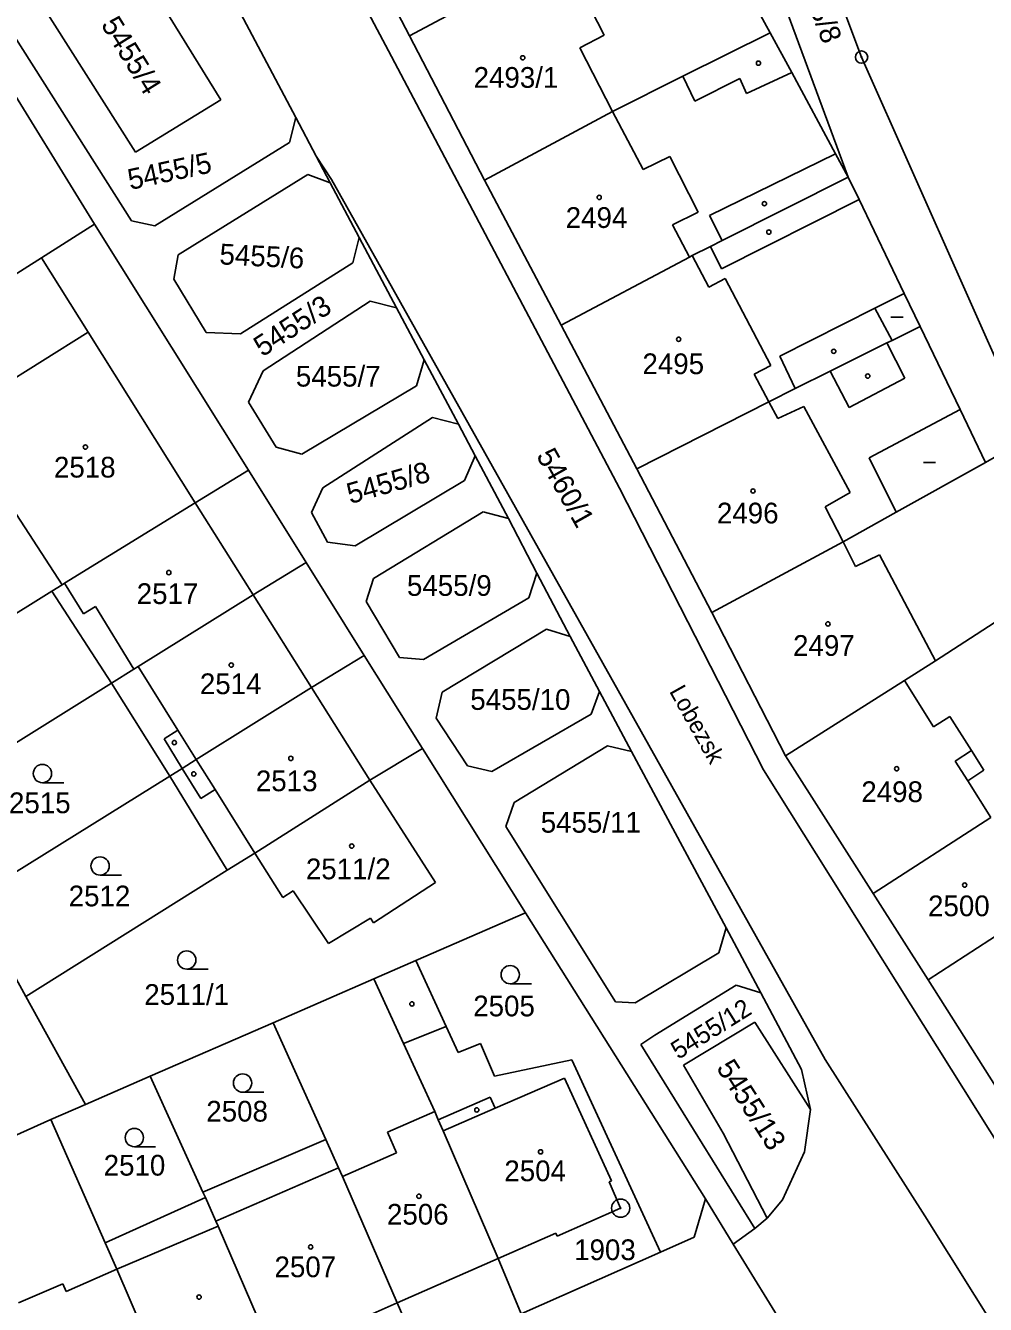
# Model space of a CAD drawing. Extents: x -822293 to -820259, y -1071573 to -1068794.
# Drawn here: x -820751.7 to -820673, y -1071232.4 to -1071127.6 of the extents above; entities that cross this region are included whole.
import ezdxf

# ---------------------------------------------------------------- set-up
doc = ezdxf.new("R2010")
doc.units = 0
for name, color, linetype in [('Vrstva 1', 7, 'Continuous'), ('Vrstva 15', 7, 'Continuous'), ('Vrstva 16', 7, 'Continuous'), ('Vrstva 17', 7, 'Continuous'), ('Vrstva 18', 7, 'Continuous'), ('Vrstva 19', 7, 'Continuous'), ('Vrstva 2', 7, 'Continuous'), ('Vrstva 24', 7, 'Continuous'), ('Vrstva 25', 7, 'Continuous'), ('Vrstva 3', 7, 'Continuous'), ('Vrstva 4', 7, 'Continuous')]:
    doc.layers.add(name, color=color, linetype=linetype)

msp = doc.modelspace()

# ---------------------------------------------------------------- linework, layer by layer
at = {"layer": 'Vrstva 1'}
for p, q in [((-820734.74, -1071105.53), (-820721.97, -1071129.66)), ((-820686.65, -1071120.86), (-820683.15, -1071130.16)), ((-820753.41, -1071121.15), (-820742.72, -1071137.97)), ((-820691.22, -1071121.15), (-820684.26, -1071140)), ((-820743.05, -1071143.59), (-820756.22, -1071122.85)), ((-820735.43, -1071124.06), (-820729.58, -1071135.12)), ((-820735.71, -1071133.66), (-820741.22, -1071124.78)), ((-820690.65, -1071128.16), (-820692.2, -1071125.31)), ((-820746.09, -1071143.86), (-820755.45, -1071128.7)), ((-820703.01, -1071165.5), (-820721.97, -1071129.66)), ((-820683.15, -1071130.16), (-820669.33, -1071161.28)), ((-820685.28, -1071138.1), (-820688.88, -1071131.43)), ((-820703.6, -1071134.61), (-820697.81, -1071131.73)), ((-820742.72, -1071137.97), (-820735.71, -1071133.66)), ((-820729.58, -1071135.12), (-820730.1, -1071137.16)), ((-820729.58, -1071135.12), (-820727.9, -1071138.28)), ((-820730.1, -1071137.16), (-820741.14, -1071144)), ((-820727.9, -1071138.28), (-820726.63, -1071140.19)), ((-820726.75, -1071140.46), (-820727.9, -1071138.28)), ((-820739.23, -1071146.37), (-820728.58, -1071139.78)), ((-820728.58, -1071139.78), (-820726.75, -1071140.46)), ((-820724.37, -1071144.96), (-820726.75, -1071140.46)), ((-820726.63, -1071140.19), (-820686.13, -1071212.37)), ((-820679.65, -1071149.54), (-820683.36, -1071141.85)), ((-820750.44, -1071146.62), (-820746.09, -1071143.86)), ((-820733.45, -1071164.03), (-820746.09, -1071143.86)), ((-820741.14, -1071144), (-820743.05, -1071143.59)), ((-820724.37, -1071144.96), (-820724.9, -1071147.03)), ((-820721.3, -1071150.72), (-820724.37, -1071144.96)), ((-820697.05, -1071146.44), (-820695.55, -1071145.68)), ((-820759.61, -1071152.44), (-820750.44, -1071146.62)), ((-820746.61, -1071152.71), (-820750.44, -1071146.62)), ((-820739.58, -1071148.36), (-820739.23, -1071146.37)), ((-820724.9, -1071147.03), (-820734.12, -1071152.85)), ((-820736.92, -1071152.74), (-820739.58, -1071148.36)), ((-820732.26, -1071155.89), (-820723.48, -1071150.17)), ((-820723.48, -1071150.17), (-820721.3, -1071150.72)), ((-820719.03, -1071154.99), (-820721.3, -1071150.72)), ((-820678.34, -1071152.24), (-820675.07, -1071159.07)), ((-820734.12, -1071152.85), (-820736.92, -1071152.74)), ((-820719.03, -1071154.99), (-820719.68, -1071157.13)), ((-820716.23, -1071160.25), (-820719.03, -1071154.99)), ((-820733.46, -1071158.47), (-820732.26, -1071155.89)), ((-820719.68, -1071157.13), (-820729.09, -1071162.72)), ((-820690.77, -1071158.42), (-820688.61, -1071157.34)), ((-820731.17, -1071162.15), (-820733.46, -1071158.47)), ((-820727.36, -1071165.47), (-820718.35, -1071159.72)), ((-820718.35, -1071159.72), (-820716.23, -1071160.25)), ((-820714.86, -1071162.86), (-820716.23, -1071160.25)), ((-820672.99, -1071163.41), (-820669.33, -1071161.28)), ((-820729.09, -1071162.72), (-820731.17, -1071162.15)), ((-820714.86, -1071162.86), (-820715.72, -1071164.88)), ((-820712.13, -1071168.01), (-820714.86, -1071162.86)), ((-820733.45, -1071164.03), (-820737.82, -1071166.7)), ((-820728.72, -1071171.6), (-820733.45, -1071164.03)), ((-820715.72, -1071164.88), (-820724.71, -1071170.23)), ((-820728.29, -1071167.5), (-820727.36, -1071165.47)), ((-820691.2, -1071188.61), (-820703.01, -1071165.5)), ((-820726.97, -1071169.93), (-820728.29, -1071167.5)), ((-820723.2, -1071172.93), (-820714.21, -1071167.44)), ((-820714.21, -1071167.44), (-820712.13, -1071168.01)), ((-820709.79, -1071172.49), (-820712.13, -1071168.01)), ((-820684.65, -1071169.9), (-820680.32, -1071167.47)), ((-820724.71, -1071170.23), (-820726.97, -1071169.93)), ((-820728.72, -1071171.6), (-820733.07, -1071174.25)), ((-820723.95, -1071179.23), (-820728.72, -1071171.6)), ((-820748.75, -1071173.43), (-820749.58, -1071173.96)), ((-820723.79, -1071174.81), (-820723.2, -1071172.93)), ((-820709.79, -1071172.49), (-820710.46, -1071174.49)), ((-820707.06, -1071177.66), (-820709.79, -1071172.49)), ((-820749.58, -1071173.96), (-820764.83, -1071183.43)), ((-820749.58, -1071173.96), (-820744.7, -1071181.5)), ((-820710.46, -1071174.49), (-820719.09, -1071179.55)), ((-820721.07, -1071179.4), (-820723.79, -1071174.81)), ((-820677.09, -1071179.67), (-820672.26, -1071176.55)), ((-820717.55, -1071182.25), (-820708.99, -1071177.07)), ((-820708.99, -1071177.07), (-820707.06, -1071177.66)), ((-820704.64, -1071182.18), (-820707.06, -1071177.66)), ((-820723.95, -1071179.23), (-820728.29, -1071181.85)), ((-820719.18, -1071186.85), (-820723.95, -1071179.23)), ((-820719.09, -1071179.55), (-820721.07, -1071179.4)), ((-820742.85, -1071180.34), (-820744.7, -1071181.5)), ((-820744.7, -1071181.5), (-820760.46, -1071191.35)), ((-820744.7, -1071181.5), (-820739.92, -1071189.13)), ((-820718.06, -1071184.38), (-820717.55, -1071182.25)), ((-820704.64, -1071182.18), (-820705.34, -1071184.04)), ((-820702.02, -1071187.09), (-820704.64, -1071182.18)), ((-820715.48, -1071188.28), (-820718.06, -1071184.38)), ((-820705.34, -1071184.04), (-820713.49, -1071188.75)), ((-820719.18, -1071186.85), (-820723.51, -1071189.45)), ((-820710.73, -1071200.33), (-820719.18, -1071186.85)), ((-820704, -1071186.65), (-820711.66, -1071191.28)), ((-820702.02, -1071187.09), (-820704, -1071186.65)), ((-820694.27, -1071201.56), (-820702.02, -1071187.09)), ((-820739.92, -1071189.13), (-820756.13, -1071199.21)), ((-820738.89, -1071188.49), (-820739.92, -1071189.13)), ((-820739.92, -1071189.13), (-820735.19, -1071196.84)), ((-820713.49, -1071188.75), (-820715.48, -1071188.28)), ((-820671.47, -1071220.04), (-820691.2, -1071188.61)), ((-820711.66, -1071191.28), (-820712.35, -1071193.24)), ((-820712.35, -1071193.24), (-820703.35, -1071207.63)), ((-820732.94, -1071195.44), (-820735.19, -1071196.84)), ((-820735.19, -1071196.84), (-820751.73, -1071207.19)), ((-820710.73, -1071200.33), (-820719.73, -1071204.25)), ((-820695.95, -1071223.78), (-820710.73, -1071200.33)), ((-820694.85, -1071203.6), (-820694.27, -1071201.56)), ((-820691.41, -1071206.9), (-820694.27, -1071201.56)), ((-820701.73, -1071207.7), (-820694.85, -1071203.6)), ((-820751.73, -1071207.19), (-820752.85, -1071205.14)), ((-820723.18, -1071205.75), (-820731.44, -1071209.34)), ((-820693.45, -1071206.27), (-820700.1, -1071210.35)), ((-820691.41, -1071206.9), (-820693.45, -1071206.27)), ((-820688.08, -1071213.18), (-820691.41, -1071206.9)), ((-820746.84, -1071216.04), (-820751.73, -1071207.19)), ((-820703.35, -1071207.63), (-820701.73, -1071207.7)), ((-820731.44, -1071209.34), (-820741.52, -1071213.72)), ((-820727.11, -1071218.91), (-820731.44, -1071209.34)), ((-820716.25, -1071211.79), (-820717.24, -1071209.64)), ((-820691.91, -1071209.29), (-820697.76, -1071212.83)), ((-820687.34, -1071216.45), (-820691.91, -1071209.29)), ((-820720.73, -1071211.06), (-820718.17, -1071216.61)), ((-820714.42, -1071211.06), (-820716.25, -1071211.79)), ((-820713.26, -1071213.73), (-820714.42, -1071211.06)), ((-820700.1, -1071210.35), (-820701.25, -1071211.14)), ((-820701.25, -1071211.14), (-820691.91, -1071226.22)), ((-820706.91, -1071212.38), (-820713.26, -1071213.73)), ((-820699.66, -1071228.17), (-820706.91, -1071212.38)), ((-820697.76, -1071212.83), (-820694.5, -1071218.41)), ((-820687.34, -1071216.45), (-820688.08, -1071213.18)), ((-820686.13, -1071212.37), (-820677.95, -1071225.19)), ((-820741.52, -1071213.72), (-820746.84, -1071216.04)), ((-820741.52, -1071213.72), (-820737.19, -1071223.25)), ((-820746.84, -1071216.04), (-820749.66, -1071217.29)), ((-820687.82, -1071219.92), (-820687.34, -1071216.45)), ((-820749.66, -1071217.29), (-820757.43, -1071220.74)), ((-820745.21, -1071227.39), (-820749.66, -1071217.29)), ((-820694.5, -1071218.41), (-820690.91, -1071225.38)), ((-820737.19, -1071223.25), (-820727.11, -1071218.91)), ((-820726.06, -1071221.23), (-820727.11, -1071218.91)), ((-820689.63, -1071223.86), (-820687.82, -1071219.92)), ((-820745.21, -1071227.39), (-820736.99, -1071223.68)), ((-820737.19, -1071223.25), (-820736.99, -1071223.68)), ((-820736.99, -1071223.68), (-820736.12, -1071225.62)), ((-820696.89, -1071226.94), (-820695.95, -1071223.78)), ((-820693.68, -1071227.51), (-820695.95, -1071223.78)), ((-820690.91, -1071225.38), (-820689.63, -1071223.86)), ((-820691.91, -1071226.22), (-820690.91, -1071225.38)), ((-820622.76, -1071313.08), (-820677.95, -1071225.19)), ((-820699.66, -1071228.17), (-820696.89, -1071226.94)), ((-820693.68, -1071227.51), (-820691.91, -1071226.22)), ((-820744.25, -1071229.56), (-820745.21, -1071227.39)), ((-820688.09, -1071236.58), (-820693.68, -1071227.51)), ((-820712.97, -1071228.69), (-820711.07, -1071233.22)), ((-820711.07, -1071233.22), (-820699.66, -1071228.17)), ((-820719.29, -1071236.82), (-820721.25, -1071232.32))]:
    msp.add_line(p, q, dxfattribs=at)
at = {"layer": 'Vrstva 2'}
for p, q in [((-820726.4, -1071116.5), (-820720.24, -1071128.42)), ((-820720.24, -1071128.42), (-820709.67, -1071122.78)), ((-820714.09, -1071140.25), (-820720.24, -1071128.42)), ((-820697.81, -1071131.73), (-820690.65, -1071128.16)), ((-820688.88, -1071131.43), (-820690.65, -1071128.16)), ((-820714.09, -1071140.25), (-820703.6, -1071134.61)), ((-820684.26, -1071140), (-820685.28, -1071138.1)), ((-820707.79, -1071152.15), (-820714.09, -1071140.25)), ((-820694.58, -1071145.2), (-820684.26, -1071140)), ((-820683.36, -1071141.85), (-820684.26, -1071140)), ((-820695.55, -1071145.68), (-820694.58, -1071145.2)), ((-820707.79, -1071152.15), (-820697.27, -1071146.56)), ((-820697.27, -1071146.56), (-820697.05, -1071146.44)), ((-820678.34, -1071152.24), (-820679.65, -1071149.54)), ((-820701.58, -1071163.92), (-820707.79, -1071152.15)), ((-820680.65, -1071153.39), (-820678.34, -1071152.24)), ((-820757.69, -1071159.67), (-820746.61, -1071152.71)), ((-820685.72, -1071155.91), (-820681.07, -1071153.6)), ((-820681.07, -1071153.6), (-820680.65, -1071153.39)), ((-820688.61, -1071157.34), (-820685.72, -1071155.91)), ((-820701.58, -1071163.92), (-820690.77, -1071158.42)), ((-820675.07, -1071159.07), (-820672.99, -1071163.41)), ((-820695.43, -1071175.71), (-820701.58, -1071163.92)), ((-820680.32, -1071167.47), (-820672.99, -1071163.41)), ((-820737.82, -1071166.7), (-820748.54, -1071173.3)), ((-820748.75, -1071173.43), (-820752.48, -1071167.68)), ((-820695.43, -1071175.71), (-820684.65, -1071169.9)), ((-820748.54, -1071173.3), (-820748.75, -1071173.43)), ((-820733.07, -1071174.25), (-820742.51, -1071180.13)), ((-820689.38, -1071187.46), (-820695.43, -1071175.71)), ((-820679.64, -1071181.29), (-820677.09, -1071179.67)), ((-820742.51, -1071180.13), (-820742.85, -1071180.34)), ((-820728.29, -1071181.85), (-820737.74, -1071187.76)), ((-820689.38, -1071187.46), (-820679.64, -1071181.29)), ((-820737.74, -1071187.76), (-820738.89, -1071188.49)), ((-820682.2, -1071198.75), (-820689.38, -1071187.46)), ((-820723.51, -1071189.45), (-820732.94, -1071195.44)), ((-820723.51, -1071189.45), (-820718.1, -1071197.85)), ((-820682.2, -1071198.75), (-820672.54, -1071192.52)), ((-820730.64, -1071199.07), (-820732.94, -1071195.44)), ((-820729.79, -1071198.53), (-820730.64, -1071199.07)), ((-820726.88, -1071202.84), (-820729.79, -1071198.53)), ((-820718.1, -1071197.85), (-820723.2, -1071201.15)), ((-820677.69, -1071205.82), (-820682.2, -1071198.75)), ((-820677.69, -1071205.82), (-820668.05, -1071199.57)), ((-820723.45, -1071200.77), (-820726.88, -1071202.84)), ((-820723.2, -1071201.15), (-820723.45, -1071200.77)), ((-820719.73, -1071204.25), (-820723.18, -1071205.75)), ((-820717.24, -1071209.64), (-820719.73, -1071204.25)), ((-820723.18, -1071205.75), (-820720.73, -1071211.06)), ((-820669.63, -1071218.58), (-820677.69, -1071205.82)), ((-820718.17, -1071216.61), (-820717.88, -1071217.3)), ((-820717.88, -1071217.3), (-820717.48, -1071218.21)), ((-820717.48, -1071218.21), (-820712.97, -1071228.69)), ((-820725.74, -1071221.95), (-820726.06, -1071221.23)), ((-820721.25, -1071232.32), (-820725.74, -1071221.95)), ((-820736.12, -1071225.62), (-820735.94, -1071226.03)), ((-820735.94, -1071226.03), (-820731.32, -1071236.74)), ((-820739.57, -1071240.36), (-820744.25, -1071229.56))]:
    msp.add_line(p, q, dxfattribs=at)
at = {"layer": 'Vrstva 24'}
for centre, radius in [((-820683.15, -1071130.16), 0.5), ((-820683.15, -1071130.16), 0.0327), ((-820702.92, -1071224.55), 0.75), ((-820702.92, -1071224.55), 0.0327)]:
    msp.add_circle(centre, radius, dxfattribs=at)
at = {"layer": 'Vrstva 25'}
for p, q in [((-820680.75, -1071151.49), (-820679.75, -1071151.49)), ((-820678.08, -1071163.4), (-820677.08, -1071163.4)), ((-820748.61, -1071189.66), (-820750.36, -1071189.66)), ((-820743.88, -1071197.24), (-820745.63, -1071197.24)), ((-820736.77, -1071204.95), (-820738.52, -1071204.95)), ((-820710.23, -1071206.15), (-820711.98, -1071206.15)), ((-820732.19, -1071215.04), (-820733.94, -1071215.04)), ((-820741.07, -1071219.51), (-820742.82, -1071219.51))]:
    msp.add_line(p, q, dxfattribs=at)
for centre, radius in [((-820710.95, -1071130.22), 0.175), ((-820691.61, -1071130.66), 0.175), ((-820704.68, -1071141.67), 0.175), ((-820691.12, -1071142.18), 0.175), ((-820690.76, -1071144.51), 0.175), ((-820698.16, -1071153.3), 0.175), ((-820685.43, -1071154.29), 0.175), ((-820682.64, -1071156.32), 0.175), ((-820746.83, -1071162.14), 0.175), ((-820692.06, -1071165.74), 0.175), ((-820739.99, -1071172.43), 0.175), ((-820685.91, -1071176.64), 0.175), ((-820734.87, -1071180.02), 0.175), ((-820739.54, -1071186.37), 0.175), ((-820750.36, -1071188.91), 0.75), ((-820729.98, -1071187.67), 0.175), ((-820737.94, -1071188.94), 0.175), ((-820680.27, -1071188.52), 0.175), ((-820724.98, -1071194.86), 0.175), ((-820745.63, -1071196.49), 0.75), ((-820674.69, -1071198.06), 0.175), ((-820738.52, -1071204.2), 0.75), ((-820711.98, -1071205.4), 0.75), ((-820720.05, -1071207.8), 0.175), ((-820733.94, -1071214.29), 0.75), ((-820714.72, -1071216.49), 0.175), ((-820742.82, -1071218.76), 0.75), ((-820709.49, -1071219.93), 0.175), ((-820719.47, -1071223.57), 0.175), ((-820728.35, -1071227.73), 0.175), ((-820737.51, -1071231.84), 0.175)]:
    msp.add_circle(centre, radius, dxfattribs=at)
at = {"layer": 'Vrstva 3'}
for p, q in [((-820704.26, -1071128.35), (-820706.15, -1071124.68)), ((-820706.28, -1071129.39), (-820704.26, -1071128.35)), ((-820703.6, -1071134.61), (-820706.28, -1071129.39)), ((-820688.88, -1071131.43), (-820692.6, -1071133.15)), ((-820696.84, -1071133.78), (-820697.81, -1071131.73)), ((-820693.14, -1071131.91), (-820696.84, -1071133.78)), ((-820692.6, -1071133.15), (-820693.14, -1071131.91)), ((-820701.07, -1071139.39), (-820703.6, -1071134.61)), ((-820698.88, -1071138.32), (-820701.07, -1071139.39)), ((-820696.55, -1071142.87), (-820698.88, -1071138.32)), ((-820695.63, -1071143.15), (-820685.28, -1071138.1)), ((-820694.63, -1071147.52), (-820683.36, -1071141.85)), ((-820698.66, -1071143.92), (-820696.55, -1071142.87)), ((-820697.27, -1071146.56), (-820698.66, -1071143.92)), ((-820694.58, -1071145.2), (-820695.63, -1071143.15)), ((-820695.55, -1071145.68), (-820694.63, -1071147.52)), ((-820695.69, -1071149.02), (-820697.05, -1071146.44)), ((-820694.33, -1071148.31), (-820695.69, -1071149.02)), ((-820690.59, -1071155.45), (-820694.33, -1071148.31)), ((-820682.06, -1071150.75), (-820679.65, -1071149.54)), ((-820689.87, -1071154.68), (-820682.06, -1071150.75)), ((-820682.06, -1071150.75), (-820680.65, -1071153.39)), ((-820737.82, -1071166.7), (-820746.61, -1071152.71)), ((-820681.07, -1071153.6), (-820679.6, -1071156.49)), ((-820691.95, -1071156.16), (-820690.59, -1071155.45)), ((-820688.61, -1071157.34), (-820689.87, -1071154.68)), ((-820690.77, -1071158.42), (-820691.95, -1071156.16)), ((-820684.17, -1071158.9), (-820685.72, -1071155.91)), ((-820679.6, -1071156.49), (-820684.17, -1071158.9)), ((-820690.02, -1071159.79), (-820690.77, -1071158.42)), ((-820687.88, -1071158.82), (-820690.02, -1071159.79)), ((-820684.09, -1071165.86), (-820687.88, -1071158.82)), ((-820682.54, -1071163.02), (-820675.07, -1071159.07)), ((-820680.32, -1071167.47), (-820682.54, -1071163.02)), ((-820686.14, -1071167.03), (-820684.09, -1071165.86)), ((-820733.07, -1071174.25), (-820737.82, -1071166.7)), ((-820684.65, -1071169.9), (-820686.14, -1071167.03)), ((-820683.66, -1071171.93), (-820684.65, -1071169.9)), ((-820681.68, -1071170.97), (-820683.66, -1071171.93)), ((-820677.09, -1071179.67), (-820681.68, -1071170.97)), ((-820747, -1071175.82), (-820748.54, -1071173.3)), ((-820728.29, -1071181.85), (-820733.07, -1071174.25)), ((-820746, -1071175.2), (-820747, -1071175.82)), ((-820742.85, -1071180.34), (-820746, -1071175.2)), ((-820739.25, -1071185.34), (-820742.51, -1071180.13)), ((-820723.51, -1071189.45), (-820728.29, -1071181.85)), ((-820677.24, -1071185.08), (-820679.64, -1071181.29)), ((-820675.91, -1071184.23), (-820677.24, -1071185.08)), ((-820674.13, -1071187.01), (-820675.91, -1071184.23)), ((-820740.38, -1071186.07), (-820739.25, -1071185.34)), ((-820738.89, -1071188.49), (-820740.38, -1071186.07)), ((-820737.74, -1071187.76), (-820739.25, -1071185.34)), ((-820674.13, -1071187.01), (-820675.47, -1071187.9)), ((-820736.2, -1071190.23), (-820737.74, -1071187.76)), ((-820675.47, -1071187.9), (-820674.44, -1071189.52)), ((-820737.37, -1071190.95), (-820738.89, -1071188.49)), ((-820736.2, -1071190.23), (-820737.37, -1071190.95)), ((-820732.94, -1071195.44), (-820736.2, -1071190.23)), ((-820672.54, -1071192.52), (-820674.44, -1071189.52)), ((-820717.24, -1071209.64), (-820720.73, -1071211.06)), ((-820707.52, -1071213.89), (-820713.22, -1071216.36)), ((-820703.68, -1071222.3), (-820707.52, -1071213.89)), ((-820713.62, -1071215.45), (-820717.88, -1071217.3)), ((-820713.22, -1071216.36), (-820713.62, -1071215.45)), ((-820713.22, -1071216.36), (-820717.48, -1071218.21)), ((-820722.04, -1071218.33), (-820718.17, -1071216.61)), ((-820721.31, -1071220), (-820722.04, -1071218.33)), ((-820725.74, -1071221.95), (-820721.31, -1071220)), ((-820736.12, -1071225.62), (-820726.06, -1071221.23)), ((-820703.86, -1071222.38), (-820703.68, -1071222.3)), ((-820702.92, -1071224.55), (-820703.86, -1071222.38)), ((-820702.92, -1071224.55), (-820708.14, -1071226.84)), ((-820744.25, -1071229.56), (-820735.94, -1071226.03)), ((-820708.24, -1071226.61), (-820712.97, -1071228.69)), ((-820708.14, -1071226.84), (-820708.24, -1071226.61)), ((-820712.97, -1071228.69), (-820721.25, -1071232.32)), ((-820748.42, -1071231.37), (-820744.25, -1071229.56)), ((-820752.32, -1071232.32), (-820748.7, -1071230.75)), ((-820748.7, -1071230.75), (-820748.42, -1071231.37)), ((-820721.25, -1071232.32), (-820731.32, -1071236.74))]:
    msp.add_line(p, q, dxfattribs=at)
at = {"layer": 'Vrstva 4'}
for p, q in [((-820673.11, -1071188.62), (-820674.13, -1071187.01)), ((-820674.44, -1071189.52), (-820673.11, -1071188.62))]:
    msp.add_line(p, q, dxfattribs=at)

# ---------------------------------------------------------------- texts
at = {"layer": 'Vrstva 15'}
msp.add_text('Lobezsk\xa0', height=1.4, rotation=299.2968, dxfattribs=at).set_placement((-820698.964, -1071182.162))
at = {"layer": 'Vrstva 16'}
msp.add_text('2483/8', height=1.7, rotation=290.26548, dxfattribs=at).set_placement((-820688.72, -1071122.666))
at = {"layer": 'Vrstva 17'}
msp.add_text('1903', height=1.7, dxfattribs=at).set_placement((-820706.735, -1071228.81))
at = {"layer": 'Vrstva 18'}
for s, height, rotation, p in [('5455/4', 1.7, 301.8195, (-820745.606, -1071127.498)), ('5455/5', 1.7, 12.1617, (-820743.156, -1071141.062)), ('5455/6', 1.7, 357.05727, (-820735.867, -1071147.152)), ('5455/3', 1.7, 33.08328, (-820732.31, -1071154.79)), ('5460/1', 1.7, 299.2968, (-820709.881, -1071162.841)), ('5455/8', 1.7, 15.83721, (-820725.108, -1071166.821)), ('5455/12', 1.5, 31.97835, (-820698.191, -1071212.398)), ('5455/13', 1.7, 302.54877, (-820695.111, -1071213.046))]:
    msp.add_text(s, height=height, rotation=rotation, dxfattribs=at).set_placement(p)
for s, p in [('5455/7', (-820729.566, -1071157.18)), ('5455/9', (-820720.452, -1071174.34)), ('5455/10', (-820715.256, -1071183.69)), ('2515', (-820753.104, -1071192.16)), ('5455/11', (-820709.476, -1071193.76)), ('2512', (-820748.207, -1071199.8)), ('2511/1', (-820742.003, -1071207.88)), ('2505', (-820715.014, -1071208.82)), ('2508', (-820736.916, -1071217.45)), ('2510', (-820745.336, -1071221.88))]:
    msp.add_text(s, height=1.7, dxfattribs=at).set_placement(p)
at = {"layer": 'Vrstva 19'}
for s, p in [('2493/1', (-820714.982, -1071132.68)), ('2494', (-820707.428, -1071144.17)), ('2495', (-820701.129, -1071156.16)), ('2518', (-820749.416, -1071164.64)), ('2496', (-820695.018, -1071168.4)), ('2517', (-820742.626, -1071175.01)), ('2497', (-820688.772, -1071179.26)), ('2514', (-820737.442, -1071182.4)), ('2513', (-820732.849, -1071190.36)), ('2498', (-820683.172, -1071191.25)), ('2511/2', (-820728.745, -1071197.58)), ('2500', (-820677.696, -1071200.61)), ('2504', (-820712.462, -1071222.34)), ('2506', (-820722.092, -1071225.9)), ('2507', (-820731.318, -1071230.21))]:
    msp.add_text(s, height=1.7, dxfattribs=at).set_placement(p)

doc.saveas('drawing.dxf')
